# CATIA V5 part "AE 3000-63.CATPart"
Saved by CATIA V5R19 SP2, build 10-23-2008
Part number: AE 3000-63
Bounding box of the stored display mesh (mm): x -47.487 to 47.487, y -47.487 to 47.487, z 0 to 197
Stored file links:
  C:\Users\Bora\Desktop\3D Katı model\AE serisi\AE 3000\AE 3000-63.CATPart
  C:\Program Files\Dassault Systemes\B19\intel_a\reffiles\standard\MetricThickPitch.txt
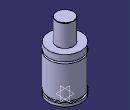
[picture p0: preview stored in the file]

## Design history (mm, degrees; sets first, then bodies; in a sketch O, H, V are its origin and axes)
Body1 (main body)
  Sketch1 on yz-plane, origin (0, 0, 0), H (0, 1, 0), V (0, 0, 1)
    point P1 (47.5, 114.5)
    point P5 (25, 196)
    point P7 (25, 196)
    point P12 (47.5, 109.5)
    point P13 (47.5, 114.5)
    point P14 (47.5, 109.5)
    line L1 (47.5, 114.5) -> (47.5, 133)
    line L2 (47.5, 0) -> (47.5, 8)
    arc A1 centre (24, 196) radius 1 from (25, 196) to (24, 197) ccw
    line L3 (25, 196) -> (25, 133)
    line L4 (43.5, 15) -> (43.5, 8)
    line L5 (47.5, 15) -> (47.5, 109.5)
    arc A2 centre (47.5, 112) radius 2.5 from (47.5, 114.5) to (47.5, 109.5) ccw
    line L6 (24, 197) -> (0, 197)
    point P15 (0, 197)
    line L7 (25, 133) -> (47.5, 133)
    line L8 (0, 0) -> (47.5, 0)
    line L9 (43.5, 15) -> (47.5, 15)
    line L10 (43.5, 8) -> (47.5, 8)
    coincidence: P15 V, P1 P13, P5 P7, P12 P14
    tangency: L6 A1
    horizontal: L7 H, L8 H, L9 H, L10 H
  Shaft1: profile Sketch1, axis Sketch1.V, angle 360
  Sketch2 on face of Shaft1 from Sketch1.L8, origin (0, 0, 0), H (1, 0, 0), V (0, -1, 0)
    point P1 (30, 0)
    distance P1 V = 30
  Hole1: placed by Sketch2, at (30, 0, 0) direction (0, 0, 1), diameter 6.647, depth 13, threaded "M8", thread diameter 8, thread depth 13, pitch 1.25
  CircPattern1: of Hole1, instances 4, angular step 90, axis from xy-plane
